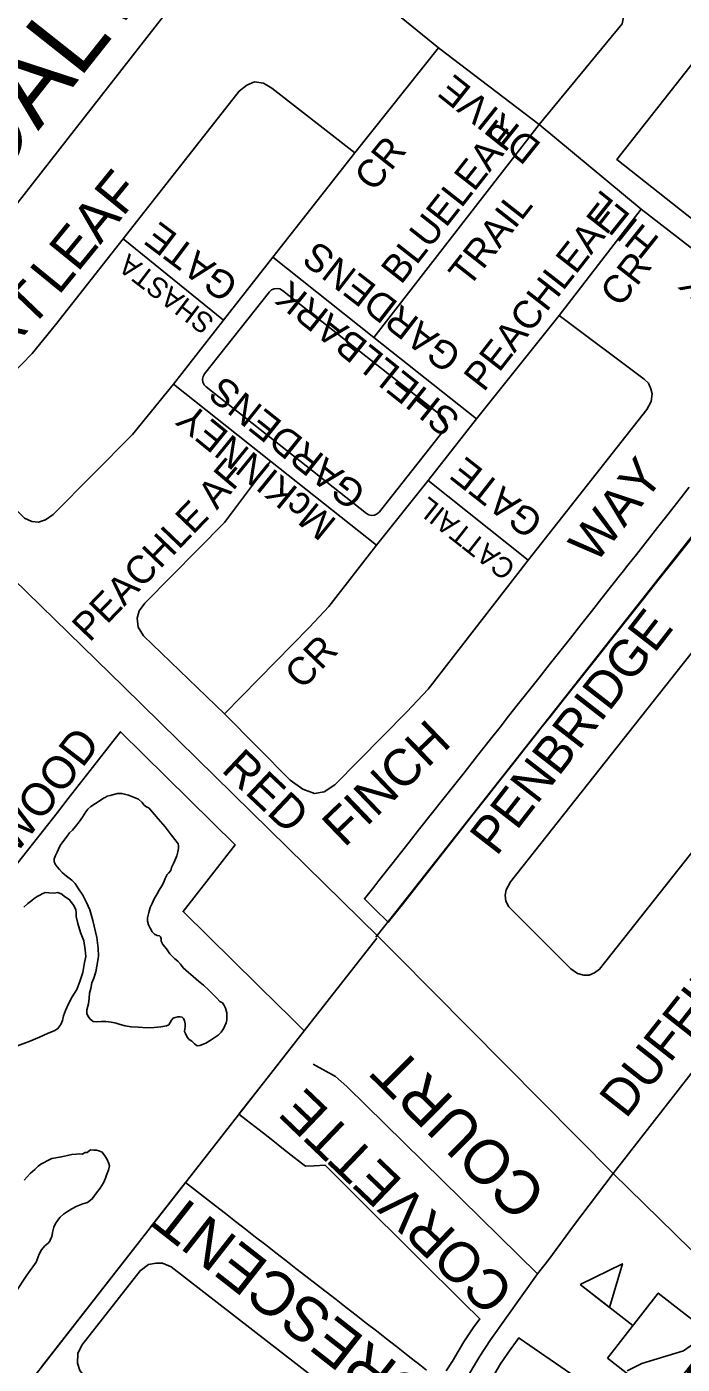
# Model space of a CAD drawing. Extents: x 586326 to 623965, y 4819854 to 4857850.
# Drawn here: x 594966 to 595318, y 4838360 to 4839080 of the extents above; entities that cross this region are included whole.
import ezdxf

# ---------------------------------------------------------------- set-up
doc = ezdxf.new("R2010")
doc.units = 0
for name, color, linetype in [('Lots_Concessions', 7, 'Continuous'), ('Major Rds and Hwys', 7, 'Continuous'), ('Major Rds Lbls', 7, 'Continuous'), ('Minor Rd Lbls', 7, 'Continuous'), ('Minor Rds', 7, 'Continuous'), ('Park Outlines', 7, 'Continuous'), ('Proposed Secondary Rds', 7, 'Continuous'), ('School Syms_Lbls', 7, 'Continuous'), ('Secondary Rds Lbls', 7, 'Continuous'), ('SWM Ponds', 7, 'Continuous')]:
    doc.layers.add(name, color=color, linetype=linetype)

msp = doc.modelspace()

# ---------------------------------------------------------------- linework, layer by layer
at = {"layer": 'Lots_Concessions'}
for p, q in [((595165.46, 4838604.55), (595580.61, 4839132.02)), ((595153.87, 4838589.81), (595165.46, 4838604.55)), ((595115.35, 4838539.52), (595154.34, 4838589.35)), ((595032.51, 4838433.46), (595115.35, 4838539.52)), ((594730.11, 4838046.4), (595032.51, 4838433.46))]:
    msp.add_line(p, q, dxfattribs=at)
at = {"layer": 'Major Rds and Hwys'}
for points in [[(594861.99, 4838876.99), (594934.54, 4838950.7), (595088.89, 4839148.46)], [(595281.37, 4838462.67), (595165.16, 4838580.18), (595155.16, 4838590.01), (595018.37, 4838724.46), (594861.99, 4838876.99)], [(595510.09, 4838236.25), (595364.54, 4838381.38), (595281.37, 4838462.67)]]:
    msp.add_lwpolyline(points, dxfattribs=at)
at = {"layer": 'Minor Rds'}
for points in [[(595136.7, 4839208.95), (595283.93, 4839096.89), (595287.38, 4839091.14), (595287.5, 4839087.39), (595286.23, 4839081.07), (595241.64, 4839026.88)], [(595142.58, 4839011.68), (595187.48, 4839068.13)], [(595018.06, 4838965.39), (595080.43, 4839044.97), (595084.45, 4839048.05), (595088.51, 4839049.91), (595093.43, 4839049.27), (595097.94, 4839046.55), (595142.58, 4839011.68)], [(595152.72, 4838912.38), (595241.64, 4839026.88)], [(595098.36, 4838955.52), (595142.58, 4839011.68)], [(595252.34, 4838924.19), (595296.48, 4838981.39)], [(595045.04, 4838887.27), (595022.97, 4838860.3), (594980.45, 4838817.27), (594976.3, 4838814.28), (594972.51, 4838813.03), (594968.85, 4838813.48), (594964.93, 4838815.14), (594929.81, 4838849.61), (594927.29, 4838853.58), (594926.76, 4838857.01), (594927.75, 4838860.85), (594930.12, 4838863.62), (594969.14, 4838903.81), (594981.57, 4838919.2), (595018.06, 4838965.39)], [(595018.06, 4838965.39), (595071.94, 4838921.71)], [(595071.94, 4838921.71), (595098.36, 4838955.52)], [(595098.36, 4838955.52), (595152.72, 4838912.38)], [(595045.04, 4838887.27), (595071.94, 4838921.71)], [(595207.91, 4838868.59), (595252.34, 4838924.19)], [(595235.62, 4838792.63), (595299.42, 4838873.66), (595301.82, 4838877.91), (595302.33, 4838882.11), (595301.66, 4838884.78), (595300.41, 4838887.9), (595298.07, 4838890.03), (595252.34, 4838924.19)], [(595152.72, 4838912.38), (595207.91, 4838868.59)], [(595045.04, 4838887.27), (595097.25, 4838845.94)], [(595181.9, 4838835.42), (595207.91, 4838868.59)], [(595072.4, 4838709.93), (595028.94, 4838751.99), (595026.1, 4838756.67), (595025.61, 4838761.44), (595026.6, 4838765.41), (595029.64, 4838769.53), (595072.4, 4838812.89), (595097.25, 4838845.94)], [(595097.25, 4838845.94), (595154.17, 4838800.66)], [(595154.17, 4838800.66), (595181.9, 4838835.42)], [(595181.9, 4838835.42), (595235.62, 4838792.63)], [(595154.17, 4838800.66), (595128.48, 4838767.66), (595118.21, 4838756.54), (595072.4, 4838709.93)], [(595072.4, 4838709.93), (595107.83, 4838674.28), (595114.58, 4838669.37), (595120.86, 4838667.17), (595126.01, 4838667.95), (595131.75, 4838671.83), (595170.42, 4838711), (595181.84, 4838723.28), (595235.62, 4838792.63)], [(595335.77, 4838650.76), (595389.87, 4838720.8), (595391.86, 4838725.39), (595391.26, 4838729.29), (595390.07, 4838732.73), (595387.39, 4838735.72), (595348.87, 4838762.86), (595343.45, 4838763.22), (595340.14, 4838762.75), (595337.89, 4838760.49), (595334.73, 4838757.03), (595226.19, 4838619.56), (595223.77, 4838615.29), (595223.35, 4838612.42), (595223.75, 4838609.15), (595225.27, 4838606.13), (595258.68, 4838572.73), (595262.19, 4838570.22), (595265.63, 4838569.36)], [(595265.63, 4838569.36), (595268.43, 4838569.45), (595271.36, 4838570.58), (595274.06, 4838572.57), (595335.77, 4838650.76)], [(595240.74, 4838408.78), (595138.22, 4838509.47), (595132.07, 4838514.87), (595120.1, 4838521.55)], [(595125.97, 4838252.99), (594997.34, 4838353.39), (594994.64, 4838356.82), (594993.49, 4838360.68), (594993.64, 4838365.95), (594995.86, 4838370.47), (595027.1, 4838410.45), (595031.61, 4838413.84), (595035.66, 4838414.52), (595039.18, 4838414.52), (595043.81, 4838412.44), (595172.16, 4838312.77)]]:
    msp.add_lwpolyline(points, dxfattribs=at)
at = {"layer": 'Park Outlines'}
for points in [[(595361.05, 4839107.15), (595283.35, 4839008.09), (595407.33, 4838910.05)], [(595322.21, 4838831.84), (595316.56, 4838824.64), (595310.92, 4838817.45), (595305.27, 4838810.25), (595299.62, 4838803.06), (595293.89, 4838795.76), (595289.26, 4838789.86), (595286.93, 4838786.89), (595284.62, 4838783.97), (595279.98, 4838778.09), (595275.33, 4838772.2), (595269.68, 4838765.05), (595264.02, 4838757.87), (595258.35, 4838750.69), (595252.68, 4838743.51), (595247.02, 4838736.33), (595241.35, 4838729.16), (595235.68, 4838721.98), (595229.83, 4838714.56), (595225.18, 4838708.68), (595220.54, 4838702.79), (595214.69, 4838695.38), (595207.95, 4838686.84), (595201.21, 4838678.31), (595195.51, 4838671.09), (595189.81, 4838663.87), (595183.58, 4838655.98), (595177.35, 4838648.09), (595171.73, 4838640.97), (595167.05, 4838635.04), (595162.38, 4838629.12), (595155.47, 4838620.38), (595152.67, 4838616.82), (595147.68, 4838610.5), (595153.15, 4838605.12), (595160.5, 4838597.88), (595165.62, 4838604.39), (595168.6, 4838608.19), (595174.35, 4838615.51), (595190.14, 4838635.6), (595199.18, 4838647.1), (595206.14, 4838655.97), (595213.11, 4838664.83), (595220.08, 4838673.7), (595227.04, 4838682.56), (595234.01, 4838691.43), (595240.97, 4838700.29), (595242.31, 4838702), (595247.97, 4838709.13), (595254.97, 4838717.97), (595261.97, 4838726.8), (595268.97, 4838735.64), (595275.98, 4838744.48), (595282.98, 4838753.31), (595289.98, 4838762.15), (595296.98, 4838770.98), (595303.99, 4838779.82), (595315.58, 4838794.45), (595317.56, 4838796.94), (595333.2, 4838816.61)], [(595191.62, 4838356.66), (595194.95, 4838361.84), (595201.15, 4838372.19), (595203.54, 4838375.97), (595206.09, 4838379.65), (595209.62, 4838384.49), (595200.8, 4838393.28), (595198.15, 4838395.91), (595195.94, 4838398.11), (595191.09, 4838402.94), (595186.24, 4838407.77), (595181.38, 4838412.61), (595176.53, 4838417.44), (595171.67, 4838422.27), (595166.82, 4838427.1), (595161.97, 4838431.93), (595157.11, 4838436.77), (595152.26, 4838441.6), (595147.41, 4838446.43), (595142.55, 4838451.26), (595137.7, 4838456.1), (595132.84, 4838460.93), (595127.99, 4838465.76), (595126.51, 4838467.23), (595120.72, 4838466.93), (595115.97, 4838466.68), (595113.86, 4838468.33), (595108.35, 4838472.64), (595103.36, 4838476.54), (595098.36, 4838480.45), (595093.36, 4838484.36), (595084.16, 4838491.55), (595080.23, 4838494.63), (595096.09, 4838514.9), (595115.34, 4838539.51), (595112.82, 4838541.99), (595106.26, 4838548.44), (595101.9, 4838552.73), (595077.33, 4838576.91), (595050.19, 4838603.63), (595078.27, 4838639.51), (595016.49, 4838700.34), (595013.71, 4838696.77), (595000.25, 4838679.54), (594988.39, 4838664.36), (594982.63, 4838656.99), (594977.28, 4838650.13), (594971.92, 4838643.28), (594966.57, 4838636.42), (594961.21, 4838629.57)], [(594974.36, 4838358.88), (595032.45, 4838433.56), (595032.67, 4838433.84), (595051.46, 4838457.86), (595067.58, 4838445.32), (595072.99, 4838441.12), (595078.39, 4838436.91), (595083.8, 4838432.71), (595089.2, 4838428.5), (595094.61, 4838424.3), (595100.02, 4838420.1), (595105.42, 4838415.89), (595110.83, 4838411.69), (595116.23, 4838407.48), (595121.64, 4838403.28), (595127.04, 4838399.08), (595132.45, 4838394.87), (595137.86, 4838390.67), (595143.26, 4838386.46), (595148.67, 4838382.26), (595154.07, 4838378.05), (595159.48, 4838373.85), (595164.89, 4838369.65), (595170.29, 4838365.44), (595175.35, 4838361.51), (595175.7, 4838361.24), (595181.11, 4838357.03)], [(595360.58, 4838359.05), (595338.51, 4838381.02), (595338.26, 4838380.84), (595319.17, 4838367.32), (595296.81, 4838360.57), (595288.95, 4838356.52)], [(595278.03, 4838341.65), (595230.92, 4838374.18), (595230.68, 4838374.35), (595224.67, 4838366.11), (595222.71, 4838363.28), (595220.87, 4838360.37), (595214.67, 4838350.02)]]:
    msp.add_lwpolyline(points, dxfattribs=at)
msp.add_lwpolyline([(595096.62, 4838936.94), (595096.62, 4838936.94), (595061.77, 4838892.87), (595061.01, 4838891.51), (595060.7, 4838889.97), (595060.88, 4838888.42), (595061.53, 4838887), (595062.59, 4838885.85), (595148.7, 4838817.76), (595150.06, 4838816.99), (595151.6, 4838816.68), (595153.15, 4838816.86), (595154.57, 4838817.52), (595155.72, 4838818.58), (595190.57, 4838862.65), (595191.34, 4838864.01), (595191.65, 4838865.55), (595191.46, 4838867.1), (595190.81, 4838868.52), (595189.75, 4838869.67), (595103.64, 4838937.76), (595102.28, 4838938.53), (595100.75, 4838938.83), (595099.2, 4838938.65), (595097.77, 4838938)], close=True, dxfattribs=at)
at = {"layer": 'Proposed Secondary Rds'}
for points in [[(595088.89, 4839148.46), (595187.48, 4839068.13)], [(595187.48, 4839068.13), (595241.64, 4839026.88)], [(595241.64, 4839026.88), (595296.48, 4838981.39)], [(595296.48, 4838981.39), (595400.33, 4838901.01), (595436.36, 4838874.85)], [(595281.37, 4838462.67), (595393.14, 4838606.12)], [(595240.74, 4838408.78), (595246.71, 4838416.41), (595260.12, 4838434.53), (595281.37, 4838462.67)], [(595172.16, 4838312.77), (595196.4, 4838343.52), (595200.85, 4838349.75), (595209.74, 4838364.55), (595215.35, 4838373.33), (595240.74, 4838408.78)]]:
    msp.add_lwpolyline(points, dxfattribs=at)
at = {"layer": 'School Syms_Lbls'}
msp.add_line((595291.97, 4838380.91), (595263.56, 4838403.1), dxfattribs=at)
for points in [[(595263.56, 4838403.1), (595286.33, 4838414.14), (595279.42, 4838390.63)], [(595278.33, 4838363.46), (595305.6, 4838398.36), (595335.21, 4838375.23), (595307.94, 4838340.33)]]:
    msp.add_lwpolyline(points, close=True, dxfattribs=at)
at = {"layer": 'SWM Ponds'}
msp.add_lwpolyline([(595031.13, 4838600.29), (595031.82, 4838603.03), (595032.58, 4838605.84), (595033.64, 4838608.03), (595034.59, 4838610.43), (595036.24, 4838613.21), (595037.33, 4838615.1), (595038.8, 4838617.49), (595039.7, 4838619.15), (595040.6, 4838621.47), (595041.59, 4838623.57), (595042.31, 4838624.32), (595043.53, 4838625.72), (595044, 4838627.33), (595045.22, 4838629.91), (595046.83, 4838633.63), (595047.3, 4838635.75), (595047.81, 4838637.58), (595047.78, 4838639.05), (595047.51, 4838640.04), (595046.53, 4838641.47), (595043.75, 4838644.95), (595040.5, 4838649.19), (595036.89, 4838653.45), (595034.83, 4838655.85), (595032.75, 4838658.39), (595031.9, 4838659.32), (595030.12, 4838660.05), (595029.19, 4838661.04), (595028.22, 4838662.32), (595026.23, 4838664.14), (595023.55, 4838665.06), (595020.82, 4838666.27), (595017.26, 4838667.08), (595014.97, 4838667.17), (595012.92, 4838666.55), (595011.07, 4838666.03), (595009.43, 4838665.61), (595008.32, 4838665.03), (595007.42, 4838664.55), (595005.04, 4838663.01), (595003.2, 4838661.82), (595000.6, 4838660.18), (594999.09, 4838658.75), (594997.88, 4838657.2), (594996.23, 4838654.42), (594994.26, 4838651.9), (594992.44, 4838649.39), (594990.85, 4838647.36), (594989.19, 4838645.91), (594987.85, 4838644.2), (594985.5, 4838641.19), (594984.13, 4838639.11), (594983.19, 4838637.22), (594982.58, 4838635.6), (594981.63, 4838633.72), (594980.96, 4838632.02), (594980.99, 4838630.55), (594981.38, 4838629.2), (594982.52, 4838627.65), (594983.74, 4838626.18), (594985.17, 4838624.67), (594987.55, 4838622.68), (594990.46, 4838620.53), (594992.16, 4838618.68), (594994.05, 4838615.9), (594996.39, 4838612.36), (594998.26, 4838608.54), (595000.08, 4838604.5), (595000.82, 4838602.09), (595001.73, 4838598.89), (595003.82, 4838589.65), (595004.51, 4838584), (595004.76, 4838579.62), (595004.32, 4838577.21), (595003.87, 4838574.28), (595003.29, 4838571.2), (595002.31, 4838567.77), (595001.23, 4838565.2), (595000.57, 4838562.18), (594999.84, 4838559.74), (594999.72, 4838557.07), (594999.29, 4838554.01), (594998.51, 4838550.82), (594998.4, 4838548.67), (594999.28, 4838546.94), (595000.23, 4838545.81), (595001.04, 4838545.17), (595001.93, 4838544.47), (595003.65, 4838544.31), (595006.21, 4838544.41), (595008.69, 4838544.57), (595011.62, 4838544.11), (595014.19, 4838543.55), (595016.4, 4838542.86), (595018.99, 4838542.15), (595022.23, 4838541.59), (595026, 4838541.39), (595030.97, 4838541.05), (595034.7, 4838541.28), (595038.26, 4838541.65), (595041.28, 4838542.13), (595042.47, 4838542.68), (595043.34, 4838543.96), (595044.01, 4838545.15), (595044.83, 4838546.21), (595045.88, 4838546.7), (595047.31, 4838547.03), (595048.57, 4838546.96), (595049.7, 4838546.73), (595050.45, 4838546.01), (595051.03, 4838544.91), (595051.38, 4838543.19), (595051.35, 4838541.64), (595051.13, 4838540.51), (595051.03, 4838539.09), (595051.51, 4838537.98), (595052.48, 4838536.04), (595053.51, 4838534.84), (595054.82, 4838533.82), (595056.32, 4838532.39), (595057.83, 4838531.47), (595059.13, 4838531.63), (595060.63, 4838532.03), (595062.44, 4838532.85), (595064.7, 4838534.23), (595066.94, 4838535.75), (595069.12, 4838537.2), (595070.61, 4838538.78), (595071.87, 4838540.55), (595072.56, 4838542.11), (595073.31, 4838543.74), (595073.78, 4838545.35), (595073.77, 4838547.19), (595073.75, 4838549.17), (595073.01, 4838551.58), (595072.12, 4838553.46), (595071.34, 4838554.46), (595069.91, 4838555.32), (595068.31, 4838556.96), (595066.26, 4838559.21), (595063.92, 4838561.57), (595061.26, 4838564.04), (595058.57, 4838566.14), (595055.69, 4838568.65), (595053.07, 4838570.83), (595050.25, 4838573.43), (595048.77, 4838575.24), (595047.38, 4838576.98), (595045.69, 4838578.17), (595043.16, 4838580.8), (595041.21, 4838583.5), (595039.3, 4838585.92), (595038.34, 4838587.71), (595038.41, 4838588.97), (595038.12, 4838590.11), (595037.47, 4838590.62), (595036.27, 4838590.77), (595034.78, 4838591.54), (595033.6, 4838592.72), (595032.55, 4838594.73), (595031.67, 4838596.46), (595030.99, 4838598.44)], close=True, dxfattribs=at)
for points in [[(594961.25, 4838531.37), (594967.42, 4838533.74), (594973.11, 4838536.06), (594977.39, 4838538.04), (594981.31, 4838539.73), (594982.89, 4838540.65), (594984.56, 4838542.79), (594985.33, 4838545.07), (594985.93, 4838547.49), (594986.94, 4838550.44), (594988.53, 4838553.94), (594990.64, 4838557.76), (594993.08, 4838561.61), (594994.73, 4838565.93), (594996.39, 4838570.82), (594997.27, 4838576.18), (594997.92, 4838579.41), (594997.63, 4838583.09), (594996.79, 4838587.91), (594995.11, 4838592.39), (594993.71, 4838597.23), (594992.77, 4838600.99), (594992.78, 4838602.85), (594992.49, 4838604.51), (594991.57, 4838606.82), (594988.98, 4838610.14), (594986.51, 4838611.77), (594985, 4838612.96), (594982.95, 4838613.84), (594980.88, 4838613.59), (594978.05, 4838613.64), (594976.01, 4838613.8), (594974.39, 4838613.19), (594973.19, 4838612.4), (594971.82, 4838611.75), (594970.09, 4838610.65), (594968.85, 4838609.6), (594966.71, 4838607.97), (594964.53, 4838605.92)], [(594960.33, 4838399.09), (594966.28, 4838407.99), (594971.16, 4838414.99), (594972.89, 4838419.41), (594974.07, 4838421.66), (594975.9, 4838423.82), (594977.68, 4838425.17), (594978.5, 4838426.41), (594979.02, 4838427.44), (594979.68, 4838428.66), (594980.04, 4838430.97), (594980.67, 4838433.8), (594981.64, 4838435.78), (594982.88, 4838437.55), (594984.05, 4838439.23), (594985.94, 4838440.92), (594988.13, 4838442.24), (594990.45, 4838443.74), (594992.66, 4838444.9), (594994.49, 4838445.77), (594996.28, 4838446.39), (594998.86, 4838447.11), (595001.37, 4838449.04), (595003.64, 4838452.31), (595005.6, 4838454.82), (595007.36, 4838457.63), (595008.5, 4838460.19), (595009.29, 4838462.31), (595010.15, 4838464.52), (595010.61, 4838466.76), (595010.27, 4838468.18), (595009.38, 4838470.17), (595008.15, 4838472.29), (595006.78, 4838474.22), (595004.84, 4838474.88), (595003.66, 4838475.22), (595002.19, 4838475.36), (595000.4, 4838475.46), (594999.59, 4838474.8), (594998.62, 4838474.11), (594997.57, 4838474.07), (594995.92, 4838473.05), (594994.76, 4838473.23), (594992.92, 4838473.09), (594990.42, 4838473.03), (594988.07, 4838472.41), (594984.85, 4838471.61), (594979.6, 4838470.81), (594977.1, 4838469.45), (594975.58, 4838468.61), (594973.66, 4838467.81), (594972.27, 4838466.59), (594970.47, 4838464.83), (594968.06, 4838462.67), (594964.76, 4838459.19)]]:
    msp.add_lwpolyline(points, dxfattribs=at)

# ---------------------------------------------------------------- texts
at = {"layer": 'Major Rds Lbls'}
msp.add_text('SANDALWOOD     ', height=39.96, rotation=51.62538, dxfattribs=at).set_placement((594880.1, 4838906.84))
at = {"layer": 'Minor Rd Lbls'}
for s, height, rotation, p in [('BLUELEAF', 15, 51.85136, (595167.34, 4838940.4)), ('CR', 15, 51.45157, (595152.87, 4838990.2)), ('LEAF', 21.6, 50.79432, (594983.29, 4838934.62)), ('TRAIL', 15, 51.87937, (595203.69, 4838938.72)), ('PEACHLEAF', 15, 51.99911, (595211.8, 4838882.62)), ('GATE', 15, 143.0065, (595080.98, 4838942.46)), ('GARDENS', 15, 142.32299, (595200.86, 4838904.32)), ('SHASTA', 10.98, 142.59111, (595067.73, 4838922.16)), ('CR', 15, 52.07341, (595285.09, 4838928.03)), ('HEART', 21.6, 46.20032, (594912.57, 4838859.12)), ('SHELLBARK', 15, 141.36926, (595200.04, 4838869.77)), ('GARDENS', 15, 141.40149, (595149.56, 4838830.43)), ('McKINNEY', 15, 140.84676, (595133.45, 4838813.87)), ('AF', 15, 49.82867, (595068.32, 4838819.25)), ('GATE', 15, 141.77234, (595244.81, 4838815.08)), ('WAY', 19.8, 51.5193, (595271.68, 4838790.1)), ('CATTAIL', 11.026, 141.77234, (595229.68, 4838789.75)), ('PEACHLE', 15, 46.20032, (594999.99, 4838748.05)), ('PENBRIDGE ', 19.8, 52.17497, (595218.62, 4838632.87)), ('CR', 15, 46.20032, (595114.29, 4838722.5)), ('FINCH', 19.8, 43.87447, (595136.91, 4838637.61)), ('SWEETWOOD ', 17.558, 52.41414, (594909.3, 4838567.75)), ('RED', 18, 316.64778, (595070.19, 4838679.37)), ('COURT', 23.76, 135.21821, (595246.83, 4838452.65)), ('CORVETTE', 21.6, 136.24279, (595229.26, 4838400.77)), ('CRESCENT', 23.76, 141.87073, (595184.73, 4838345.65))]:
    msp.add_text(s, height=height, rotation=rotation, dxfattribs=at).set_placement(p)
at = {"layer": 'School Syms_Lbls'}
for s, p in [('KINDERGARTEN', (595306.97, 4838216.89)), ('ACADEMIC ', (595267.56, 4838247.67))]:
    msp.add_text(s, height=25, rotation=52.00002, dxfattribs=at).set_placement(p)
at = {"layer": 'Secondary Rds Lbls'}
for s, height, rotation, p in [('EDENBROOK    HILL       DRIVE', 15, 141.33561, (595424.5, 4838871.45)), ('DUFFIELD    ROAD', 19.8, 51.71378, (595288.16, 4838491.69))]:
    msp.add_text(s, height=height, rotation=rotation, dxfattribs=at).set_placement(p)

doc.saveas('drawing.dxf')
